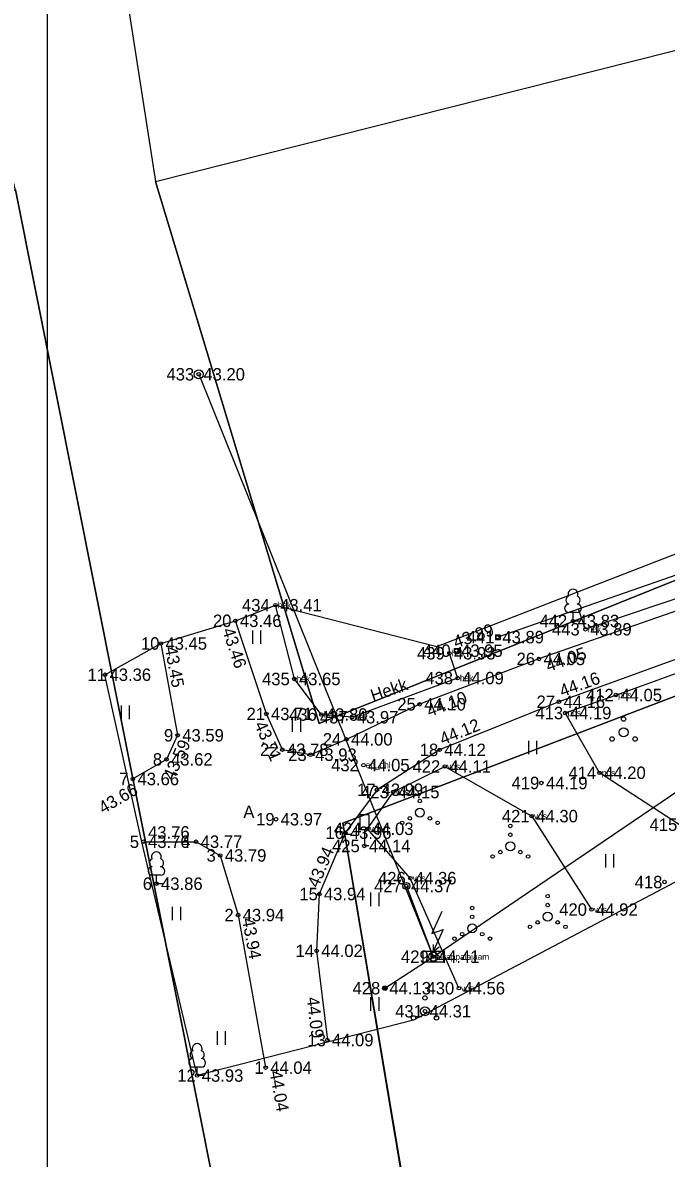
# Model space of a CAD drawing. Extents: x 505800 to 507326, y 6540058 to 6542128.
# Drawn here: x 506000.1 to 506036.4, y 6540181.8 to 6540245.8 of the extents above; entities that cross this region are included whole.
import ezdxf

# ---------------------------------------------------------------- set-up
doc = ezdxf.new("R2010")
doc.units = 0
for name, color, linetype in [('AED', 7, 'Continuous'), ('ELRAJATISMP', 7, 'Continuous'), ('HALJASTUS', 7, 'Continuous'), ('KORGUS-EH2000', 7, 'Continuous'), ('KPOHULIIN', 7, 'Continuous'), ('LIIKLUS', 7, 'Continuous'), ('MAAMUDEL', 7, 'Continuous'), ('MOOTKORG-EH2000', 7, 'Continuous'), ('MOOTMPUNKT', 7, 'Continuous'), ('MOOTNR', 7, 'Continuous'), ('MOOTPIIR', 7, 'Continuous'), ('MPOHULIIN', 7, 'Continuous'), ('PIIR', 7, 'Continuous'), ('POST', 7, 'Continuous'), ('PUU', 7, 'Continuous'), ('TEE', 7, 'Continuous'), ('VORMISTUS', 7, 'Continuous')]:
    doc.layers.add(name, color=color, linetype=linetype)

msp = doc.modelspace()

# ---------------------------------------------------------------- linework, layer by layer
at = {"layer": 'AED'}
for p, q in [((506026.798, 6540211.293), (506026.798, 6540211.043)), ((506026.798, 6540211.293), (506027.048, 6540211.293)), ((506026.798, 6540211.043), (506027.048, 6540211.043)), ((506027.048, 6540211.293), (506027.048, 6540211.043)), ((506024.47, 6540210.528), (506024.47, 6540210.278)), ((506024.47, 6540210.528), (506024.72, 6540210.528)), ((506024.47, 6540210.278), (506024.72, 6540210.278)), ((506024.72, 6540210.528), (506024.72, 6540210.278))]:
    msp.add_line(p, q, dxfattribs=at)
msp.add_lwpolyline([(506083.03, 6540240.114), (506084.929, 6540234.985), (506074.186, 6540230.116), (506061.873, 6540224.528), (506050.695, 6540219.468), (506044.19, 6540217.171), (506026.923, 6540211.168)], dxfattribs=at)
at = {"layer": 'ELRAJATISMP'}
for p, q in [((506023.764, 6540195.712), (506023.196, 6540194.47)), ((506023.196, 6540194.47), (506023.843, 6540194.694)), ((506023.843, 6540194.694), (506023.288, 6540193.465)), ((506023.885, 6540193.465), (506022.691, 6540193.465)), ((506022.691, 6540193.465), (506022.691, 6540192.869)), ((506023.152, 6540193.465), (506023.152, 6540192.869)), ((506023.288, 6540193.862), (506023.288, 6540193.465)), ((506023.288, 6540193.465), (506023.619, 6540193.73)), ((506023.424, 6540193.465), (506023.424, 6540192.869)), ((506023.885, 6540192.869), (506023.885, 6540193.465)), ((506022.691, 6540192.869), (506023.885, 6540192.869))]:
    msp.add_line(p, q, dxfattribs=at)
at = {"layer": 'HALJASTUS'}
for p, q in [((506013.098, 6540211.549), (506013.098, 6540210.787)), ((506013.553, 6540211.549), (506013.553, 6540210.787)), ((506005.691, 6540207.316), (506005.691, 6540206.555)), ((506006.146, 6540207.316), (506006.146, 6540206.555)), ((506015.34, 6540206.595), (506015.34, 6540205.834)), ((506015.795, 6540206.595), (506015.795, 6540205.834)), ((506028.653, 6540205.329), (506028.653, 6540204.568)), ((506029.108, 6540205.329), (506029.108, 6540204.568)), ((506032.997, 6540198.949), (506032.997, 6540198.188)), ((506033.452, 6540198.949), (506033.452, 6540198.188)), ((506019.755, 6540196.776), (506019.755, 6540196.015)), ((506020.21, 6540196.776), (506020.21, 6540196.015)), ((506008.574, 6540195.979), (506008.574, 6540195.218)), ((506009.029, 6540195.979), (506009.029, 6540195.218)), ((506019.755, 6540190.887), (506019.755, 6540190.126)), ((506020.21, 6540190.887), (506020.21, 6540190.126)), ((506011.096, 6540188.968), (506011.096, 6540188.207)), ((506011.551, 6540188.968), (506011.551, 6540188.207))]:
    msp.add_line(p, q, dxfattribs=at)
for points in [[(506043.655, 6540216.985), (506043.78, 6540216.669), (506044.148, 6540215.753), (506031.868, 6540211.611), (506031.473, 6540212.75)], [(506024.19, 6540210.261), (506024.657, 6540208.861), (506018.717, 6540206.657), (506016.976, 6540206.809), (506015.456, 6540208.81), (506014.395, 6540212.969)], [(506046.677, 6540204.671), (506040.966, 6540199.801), (506037.159, 6540200.603), (506032.66, 6540203.527), (506030.725, 6540206.895), (506033.579, 6540207.906), (506043.226, 6540211.399), (506047.158, 6540212.679), (506048.085, 6540210.638), (506048.426, 6540206.794), (506046.677, 6540204.671)], [(506024.726, 6540191.392), (506021.993, 6540197.592), (506019.57, 6540200.371), (506021.037, 6540202.445), (506023.935, 6540203.883), (506028.835, 6540201.086), (506032.206, 6540195.823)]]:
    msp.add_lwpolyline(points, dxfattribs=at)
for centre, radius in [((506022.531, 6540202.435), 0.1), ((506022.531, 6540201.935), 0.1), ((506022.531, 6540201.285), 0.25), ((506021.531, 6540200.71), 0.1), ((506021.966, 6540200.96), 0.1), ((506023.096, 6540200.96), 0.1), ((506023.531, 6540200.71), 0.1), ((506027.632, 6540200.535), 0.1), ((506027.632, 6540200.035), 0.1), ((506027.632, 6540199.385), 0.25), ((506026.632, 6540198.81), 0.1), ((506027.067, 6540199.06), 0.1), ((506028.197, 6540199.06), 0.1), ((506028.632, 6540198.81), 0.1), ((506029.737, 6540196.574), 0.1), ((506025.482, 6540195.91), 0.1), ((506029.737, 6540196.074), 0.1), ((506025.482, 6540195.41), 0.1), ((506029.737, 6540195.424), 0.25), ((506025.482, 6540194.76), 0.25), ((506028.737, 6540194.849), 0.1), ((506029.172, 6540195.099), 0.1), ((506030.302, 6540195.099), 0.1), ((506030.737, 6540194.849), 0.1), ((506024.482, 6540194.185), 0.1), ((506024.917, 6540194.435), 0.1), ((506026.047, 6540194.435), 0.1), ((506026.482, 6540194.185), 0.1)]:
    msp.add_circle(centre, radius, dxfattribs=at)
at = {"layer": 'KORGUS-EH2000'}
for centre in [(506010.066, 6540225.975), (506014.395, 6540212.969), (506012.129, 6540212.088), (506031.163, 6540212.076), (506031.868, 6540211.611), (506007.93, 6540210.81), (506026.923, 6540211.168), (506024.19, 6540210.261), (506024.595, 6540210.403), (506029.242, 6540209.942), (506004.777, 6540209.051), (506015.456, 6540208.81), (506024.657, 6540208.861), (506030.369, 6540207.528), (506033.579, 6540207.906), (506013.879, 6540206.842), (506016.976, 6540206.809), (506022.519, 6540207.387), (506030.725, 6540206.895), (506018.717, 6540206.657), (506008.876, 6540205.637), (506018.387, 6540205.411), (506008.246, 6540204.281), (506014.779, 6540204.825), (506016.369, 6540204.542), (506023.645, 6540204.818), (506019.349, 6540203.959), (506023.935, 6540203.883), (506006.353, 6540203.178), (506029.38, 6540202.952), (506032.66, 6540203.527), (506020.115, 6540202.573), (506021.037, 6540202.445), (506028.835, 6540201.086), (506014.422, 6540200.91), (506018.326, 6540200.153), (506019.57, 6540200.371), (506006.95, 6540199.643), (506009.915, 6540199.645), (506019.402, 6540199.405), (506011.275, 6540198.87), (506007.681, 6540197.278), (506021.993, 6540197.592), (506036.321, 6540197.372), (506016.859, 6540196.696), (506021.771, 6540197.147), (506012.284, 6540195.512), (506032.206, 6540195.823), (506016.712, 6540193.498), (506023.288, 6540193.167), (506020.555, 6540191.392), (506024.726, 6540191.392), (506022.817, 6540190.094), (506017.316, 6540188.473), (506009.976, 6540186.473), (506013.836, 6540186.918)]:
    msp.add_circle(centre, 0.1, dxfattribs=at)
at = {"layer": 'KPOHULIIN'}
msp.add_line((506010.066, 6540225.975), (506023.288, 6540193.167), dxfattribs=at)
at = {"layer": 'LIIKLUS'}
for p, q in [((506019.152, 6540201.155), (506019.152, 6540200.305)), ((506019.652, 6540201.155), (506019.152, 6540201.155)), ((506019.652, 6540201.155), (506019.652, 6540200.305)), ((506019.652, 6540200.305), (506019.152, 6540200.305)), ((506019.402, 6540200.305), (506019.402, 6540199.405)), ((506019.652, 6540199.405), (506019.402, 6540199.405))]:
    msp.add_line(p, q, dxfattribs=at)
at = {"layer": 'MOOTMPUNKT'}
for centre in [(506010.066, 6540225.975), (506014.395, 6540212.969), (506012.129, 6540212.088), (506031.163, 6540212.076), (506031.868, 6540211.611), (506007.93, 6540210.81), (506026.923, 6540211.168), (506024.19, 6540210.261), (506024.595, 6540210.403), (506029.242, 6540209.942), (506004.777, 6540209.051), (506015.456, 6540208.81), (506024.657, 6540208.861), (506030.369, 6540207.528), (506033.579, 6540207.906), (506013.879, 6540206.842), (506016.976, 6540206.809), (506022.519, 6540207.387), (506030.725, 6540206.895), (506018.717, 6540206.657), (506008.876, 6540205.637), (506018.387, 6540205.411), (506008.246, 6540204.281), (506014.779, 6540204.825), (506016.369, 6540204.542), (506023.645, 6540204.818), (506019.349, 6540203.959), (506023.935, 6540203.883), (506006.353, 6540203.178), (506029.38, 6540202.952), (506032.66, 6540203.527), (506020.115, 6540202.573), (506021.037, 6540202.445), (506028.835, 6540201.086), (506014.422, 6540200.91), (506018.326, 6540200.153), (506019.57, 6540200.371), (506006.95, 6540199.643), (506009.915, 6540199.645), (506019.402, 6540199.405), (506011.275, 6540198.87), (506007.681, 6540197.278), (506021.993, 6540197.592), (506036.321, 6540197.372), (506016.859, 6540196.696), (506021.771, 6540197.147), (506012.284, 6540195.512), (506032.206, 6540195.823), (506016.712, 6540193.498), (506023.288, 6540193.167), (506020.555, 6540191.392), (506024.726, 6540191.392), (506022.817, 6540190.094), (506017.316, 6540188.473), (506009.976, 6540186.473), (506013.836, 6540186.918)]:
    msp.add_circle(centre, 0.1, dxfattribs=at)
at = {"layer": 'MOOTPIIR'}
msp.add_lwpolyline([(506098.399, 6540223.506), (506079.917, 6540216.55), (506066.66, 6540209.695), (506043.081, 6540200.619), (506022.167, 6540189.594), (506009.976, 6540186.473), (506006.85, 6540199.643), (506004.777, 6540209.051), (506007.93, 6540210.81), (506012.129, 6540212.088), (506014.395, 6540212.969), (506023.481, 6540210.643), (506053.328, 6540222.211), (506081.494, 6540234.9), (506083.03, 6540240.114), (506097.119, 6540244.795)], dxfattribs=at)
at = {"layer": 'MPOHULIIN'}
msp.add_lwpolyline([(506023.288, 6540193.167), (506046.819, 6540209.126), (506079.898, 6540221.464), (506112.189, 6540233.927), (506117.49, 6540230.51)], dxfattribs=at)
at = {"layer": 'PIIR'}
for points in [[(505974.82, 6540373.27), (505978.55, 6540356.29), (505982.26, 6540340.2), (505984.17, 6540331.95), (505991.66, 6540295.73), (505997.71, 6540274.55), (506002.06, 6540260.07), (506006.14, 6540246.35), (506007.63, 6540236.84), (506016.86, 6540206.3), (506080.52, 6540231.87), (506081.75, 6540225.93), (506053.1, 6540214.07), (506049.36, 6540212.6), (506018.19, 6540200.68), (506024.58, 6540162.72), (506028.99, 6540136.11), (506032.48, 6540120.26), (506023.4, 6540117.76), (505999.74, 6540236.36), (505986.45, 6540288.25), (505981.09, 6540311.85), (505971.84, 6540354.07), (505949.8, 6540450)], [(506028.99, 6540136.11), (506018.19, 6540200.68), (506049.36, 6540212.6), (506053.99, 6540200.79), (506052.51, 6540200.31), (506055.45, 6540190.69), (506062.61, 6540193.04), (506059.62, 6540202.68), (506057.79, 6540202.01), (506053.1, 6540214.07), (506081.75, 6540225.93), (506090.32, 6540182.64), (506150.17, 6540208.02), (506142.88, 6540238.84), (506158.97, 6540240.95), (506187, 6540243.59), (506198.96, 6540244.45), (506208.53, 6540246.07), (506224.13, 6540249.92), (506272.39, 6540267.75)]]:
    msp.add_lwpolyline(points, dxfattribs=at)
for points in [[(506075.94, 6540254.08), (506080.52, 6540231.87), (506016.86, 6540206.3), (506007.63, 6540236.84)], [(505898.41, 6540253.45), (505905.66, 6540212.38), (505999.74, 6540236.36), (506023.4, 6540117.76), (505923.02, 6540085.38), (505883.03, 6540073.28), (505825.82, 6540058.01), (505799.77, 6540171.92), (505858.04, 6540246.52)]]:
    msp.add_lwpolyline(points, close=True, dxfattribs=at)
at = {"layer": 'POST'}
for points in [[(506021.771, 6540197.147), (506023.288, 6540193.167)], [(506020.555, 6540191.392), (506023.288, 6540193.167)]]:
    msp.add_lwpolyline(points, dxfattribs=at)
for centre, radius in [((506010.066, 6540225.975), 0.25), ((506021.771, 6540197.147), 0.2), ((506023.288, 6540193.167), 0.25), ((506020.555, 6540191.392), 0.125), ((506020.555, 6540191.392), 0.105), ((506020.555, 6540191.392), 0.0851), ((506020.555, 6540191.392), 0.0651), ((506020.555, 6540191.392), 0.0451), ((506020.555, 6540191.392), 0.0251), ((506020.555, 6540191.392), 0.00511)]:
    msp.add_circle(centre, radius, dxfattribs=at)
at = {"layer": 'PUU'}
for p, q in [((506031.404, 6540212.551), (506030.924, 6540212.551)), ((506031.163, 6540212.076), (506031.163, 6540212.551)), ((506031.544, 6540212.076), (506031.163, 6540212.076)), ((506007.921, 6540197.753), (506007.441, 6540197.753)), ((506007.681, 6540197.278), (506007.681, 6540197.753)), ((506008.061, 6540197.278), (506007.681, 6540197.278)), ((506010.216, 6540186.948), (506009.736, 6540186.948)), ((506009.976, 6540186.473), (506009.976, 6540186.948)), ((506010.356, 6540186.473), (506009.976, 6540186.473))]:
    msp.add_line(p, q, dxfattribs=at)
for centre, radius in [((506034.015, 6540206.556), 0.125), ((506034.015, 6540205.806), 0.25), ((506033.365, 6540205.431), 0.125), ((506034.665, 6540205.431), 0.125), ((506022.817, 6540190.844), 0.125), ((506022.817, 6540190.094), 0.25), ((506022.167, 6540189.719), 0.125), ((506023.467, 6540189.719), 0.125)]:
    msp.add_circle(centre, radius, dxfattribs=at)
for centre, radius, start, end in [((506030.993, 6540213.249), 0.233, 109.02174, 253.14154), ((506031.163, 6540213.596), 0.277, 332.5799, 207.4201), ((506031.334, 6540213.249), 0.233, 286.85082, 70.98591), ((506030.926, 6540212.789), 0.238, 90.0016, 269.3953), ((506031.401, 6540212.789), 0.238, 270.6047, 89.9984), ((506007.511, 6540198.45), 0.233, 109.02174, 253.14154), ((506007.681, 6540198.798), 0.277, 332.5799, 207.4201), ((506007.851, 6540198.45), 0.233, 286.85082, 70.98591), ((506007.444, 6540197.99), 0.238, 90.0016, 269.3953), ((506007.919, 6540197.99), 0.238, 270.6047, 89.9984), ((506009.806, 6540187.646), 0.233, 109.02174, 253.14154), ((506009.976, 6540187.993), 0.277, 332.5799, 207.4201), ((506010.146, 6540187.646), 0.233, 286.85082, 70.98591), ((506009.739, 6540187.186), 0.238, 90.0016, 269.3953), ((506010.214, 6540187.186), 0.238, 270.6047, 89.9984)]:
    msp.add_arc(centre, radius, start, end, dxfattribs=at)
at = {"layer": 'TEE'}
for points in [[(506136.149, 6540239.864), (506135.937, 6540240.063), (506132.254, 6540239.999), (506126.638, 6540239.842), (506117.049, 6540238.049), (506105.059, 6540234.886), (506099.56, 6540233.572), (506092.451, 6540231.789), (506085.515, 6540229.625), (506076.748, 6540225.83), (506064.781, 6540220.419), (506053.702, 6540216.033), (506042.573, 6540211.964), (506030.369, 6540207.528), (506023.645, 6540204.818), (506020.115, 6540202.573), (506018.326, 6540200.153), (506016.859, 6540196.696), (506016.712, 6540193.498), (506017.316, 6540188.473)], [(506091.024, 6540234.378), (506084.768, 6540232.16), (506075.613, 6540228.084), (506063.699, 6540222.682), (506052.876, 6540218.34), (506041.76, 6540214.299), (506029.242, 6540209.942), (506022.519, 6540207.387), (506018.387, 6540205.411), (506016.369, 6540204.542), (506014.779, 6540204.825), (506013.879, 6540206.842), (506012.129, 6540212.088)], [(506007.93, 6540210.81), (506008.876, 6540205.637), (506008.246, 6540204.281), (506006.353, 6540203.178)], [(506006.95, 6540199.643), (506009.915, 6540199.645), (506011.275, 6540198.87), (506012.284, 6540195.512), (506013.836, 6540186.918)]]:
    msp.add_lwpolyline(points, dxfattribs=at)
at = {"layer": 'VORMISTUS'}
msp.add_lwpolyline([(506001.54, 6540083.849), (506001.54, 6540499.349), (506583.541, 6540499.349), (506583.541, 6540083.849)], close=True, dxfattribs=at)

# ---------------------------------------------------------------- texts
at = {"layer": 'HALJASTUS'}
msp.add_text('Hekk', height=0.7, rotation=19.09081, dxfattribs=at).set_placement((506019.897, 6540207.515))
at = {"layer": 'KORGUS-EH2000'}
for s, p in [(' 43.41', (506014.395, 6540212.619)), (' 43.36', (506004.777, 6540208.701)), (' 44.05', (506033.579, 6540207.556)), (' 43.80', (506016.976, 6540206.459)), (' 44.11', (506023.935, 6540203.533)), (' 44.20', (506032.66, 6540203.177)), (' 44.19', (506029.38, 6540202.602)), (' 43.97', (506014.422, 6540200.56)), (' 44.03', (506019.57, 6540200.021)), (' 44.36', (506021.993, 6540197.242)), (' 43.86', (506007.681, 6540196.928)), (' 44.92', (506032.206, 6540195.473)), (' 44.31', (506022.817, 6540189.744)), (' 43.93', (506009.976, 6540186.123))]:
    msp.add_text(s, height=0.7, dxfattribs=at).set_placement(p)
for s, rotation, p in [(' 43.46', 288.44871, (506011.299, 6540211.811)), (' 43.89', 19.17139, (506024.316, 6540210.447)), (' 43.45', 280.3716, (506008.102, 6540210.841)), (' 44.05', 19.18833, (506029.53, 6540209.116)), (' 44.16', 19.97658, (506030.31, 6540207.693)), (' 44.10', 20.81373, (506022.83, 6540206.569)), (' 43.71', 294.02808, (506013.08, 6540206.486)), (' 44.12', 21.95081, (506023.58, 6540204.981)), (' 43.59', 65.06595, (506008.532, 6540202.82)), (' 43.66', 30.23121, (506004.455, 6540201.059)), (' 43.76', 0.04058, (506006.95, 6540199.818)), (' 43.94', 66.99992, (506016.698, 6540196.764)), (' 43.94', 280.23695, (506012.457, 6540195.543)), (' 44.09', 276.85824, (506016.117, 6540191.118)), (' 44.04', 280.23695, (506014.009, 6540186.949))]:
    msp.add_text(s, height=0.7, rotation=rotation, dxfattribs=at).set_placement(p)
at = {"layer": 'MAAMUDEL'}
for s, p in [(' hek', (506014.395, 6540212.794)), (' hek', (506031.868, 6540211.436)), (' hek', (506024.19, 6540210.086)), (' hek', (506015.456, 6540208.635)), (' hek', (506024.657, 6540208.686)), (' pos', (506033.579, 6540207.731)), (' hek', (506016.976, 6540206.634)), (' pos', (506030.725, 6540206.72)), (' hek', (506018.717, 6540206.482)), (' ep_ohl', (506019.349, 6540203.784)), (' vos', (506023.935, 6540203.708)), (' pos', (506032.66, 6540203.352)), (' vos', (506021.037, 6540202.27)), (' vos', (506028.835, 6540200.91)), (' vos', (506019.57, 6540200.196)), (' vos', (506021.993, 6540197.417)), (' vos', (506032.206, 6540195.648)), (' elkappalajaam', (506023.288, 6540192.992)), (' vos', (506024.726, 6540191.217))]:
    msp.add_text(s, height=0.35, dxfattribs=at).set_placement(p)
at = {"layer": 'MOOTKORG-EH2000'}
for s, p in [(' 43.20', (506010.066, 6540225.625)), (' 43.41', (506014.395, 6540212.619)), (' 43.46', (506012.129, 6540211.738)), (' 43.83', (506031.163, 6540211.726)), (' 43.89', (506026.923, 6540210.818)), (' 43.89', (506031.868, 6540211.261)), (' 43.45', (506007.93, 6540210.46)), (' 43.95', (506024.595, 6540210.053)), (' 43.93', (506024.19, 6540209.911)), (' 44.05', (506029.242, 6540209.592)), (' 43.36', (506004.777, 6540208.701)), (' 43.65', (506015.456, 6540208.46)), (' 44.09', (506024.657, 6540208.511)), (' 44.05', (506033.579, 6540207.556)), (' 44.10', (506022.519, 6540207.036)), (' 44.16', (506030.369, 6540207.178)), (' 43.71', (506013.879, 6540206.492)), (' 43.80', (506016.976, 6540206.459)), (' 43.97', (506018.717, 6540206.307)), (' 44.19', (506030.725, 6540206.545)), (' 43.59', (506008.876, 6540205.287)), (' 44.00', (506018.387, 6540205.061)), (' 43.78', (506014.779, 6540204.475)), (' 44.12', (506023.645, 6540204.468)), (' 43.62', (506008.246, 6540203.931)), (' 43.93', (506016.369, 6540204.192)), (' 44.05', (506019.349, 6540203.609)), (' 44.11', (506023.935, 6540203.533)), (' 44.20', (506032.66, 6540203.177)), (' 43.66', (506006.353, 6540202.828)), (' 44.19', (506029.38, 6540202.602)), (' 43.99', (506020.115, 6540202.223)), (' 44.15', (506021.037, 6540202.095)), (' 43.97', (506014.422, 6540200.56)), (' 44.30', (506028.835, 6540200.735)), (' 43.96', (506018.326, 6540199.803)), (' 44.03', (506019.57, 6540200.021)), (' 43.76', (506006.95, 6540199.293)), (' 43.77', (506009.915, 6540199.295)), (' 43.79', (506011.275, 6540198.52)), (' 44.14', (506019.402, 6540199.055)), (' 44.36', (506021.993, 6540197.242)), (' 43.86', (506007.681, 6540196.928)), (' 44.37', (506021.771, 6540196.797)), (' 43.94', (506016.859, 6540196.346)), (' 44.92', (506032.206, 6540195.473)), (' 43.94', (506012.284, 6540195.162)), (' 44.02', (506016.712, 6540193.148)), (' 44.41', (506023.288, 6540192.817)), (' 44.13', (506020.555, 6540191.042)), (' 44.56', (506024.726, 6540191.042)), (' 44.31', (506022.817, 6540189.744)), (' 44.09', (506017.316, 6540188.123)), (' 44.04', (506013.836, 6540186.568)), (' 43.93', (506009.976, 6540186.123))]:
    msp.add_text(s, height=0.7, dxfattribs=at).set_placement(p)
at = {"layer": 'MOOTNR'}
for s, p in [('433 ', (506008.246, 6540225.625)), ('434 ', (506012.505, 6540212.619)), ('20 ', (506010.869, 6540211.738)), ('442 ', (506029.274, 6540211.726)), ('441 ', (506025.174, 6540210.818)), ('443 ', (506029.979, 6540211.261)), ('10 ', (506006.81, 6540210.46)), ('440 ', (506022.705, 6540210.053)), ('439 ', (506022.37, 6540209.911)), ('26 ', (506027.982, 6540209.592)), ('11 ', (506003.797, 6540208.701)), ('435 ', (506013.636, 6540208.46)), ('438 ', (506022.837, 6540208.511)), ('412 ', (506031.899, 6540207.556)), ('25 ', (506021.259, 6540207.036)), ('27 ', (506029.109, 6540207.178)), ('21 ', (506012.759, 6540206.492)), ('436 ', (506015.156, 6540206.459)), ('437 ', (506016.897, 6540206.307)), ('413 ', (506029.045, 6540206.545)), ('9 ', (506008.106, 6540205.287)), ('24 ', (506017.057, 6540205.061)), ('22 ', (506013.519, 6540204.475)), ('18 ', (506022.525, 6540204.468)), ('8 ', (506007.476, 6540203.931)), ('23 ', (506015.109, 6540204.192)), ('432 ', (506017.529, 6540203.609)), ('422 ', (506022.116, 6540203.533)), ('414 ', (506030.91, 6540203.177)), ('7 ', (506005.583, 6540202.828)), ('419 ', (506027.7, 6540202.602)), ('17 ', (506018.995, 6540202.223)), ('423 ', (506019.217, 6540202.095)), ('19 ', (506013.302, 6540200.56)), ('421 ', (506027.155, 6540200.735)), ('16 ', (506017.206, 6540199.803)), ('424 ', (506017.68, 6540200.021)), ('415 ', (506035.479, 6540200.253)), ('5 ', (506006.18, 6540199.293)), ('4 ', (506009.075, 6540199.295)), ('3 ', (506010.505, 6540198.52)), ('425 ', (506017.582, 6540199.055)), ('426 ', (506020.173, 6540197.242)), ('6 ', (506006.911, 6540196.928)), ('427 ', (506019.951, 6540196.797)), ('418 ', (506034.641, 6540197.022)), ('15 ', (506015.739, 6540196.346)), ('420 ', (506030.386, 6540195.473)), ('2 ', (506011.514, 6540195.162)), ('14 ', (506015.522, 6540193.148)), ('429 ', (506021.468, 6540192.817)), ('428 ', (506018.735, 6540191.042)), ('430 ', (506022.906, 6540191.042)), ('431 ', (506021.137, 6540189.744)), ('13 ', (506016.196, 6540188.123)), ('1 ', (506013.206, 6540186.568)), ('12 ', (506008.856, 6540186.123))]:
    msp.add_text(s, height=0.7, dxfattribs=at).set_placement(p)
at = {"layer": 'TEE'}
msp.add_text('A', height=0.7, dxfattribs=at).set_placement((506012.579, 6540200.981))

doc.saveas('drawing.dxf')
